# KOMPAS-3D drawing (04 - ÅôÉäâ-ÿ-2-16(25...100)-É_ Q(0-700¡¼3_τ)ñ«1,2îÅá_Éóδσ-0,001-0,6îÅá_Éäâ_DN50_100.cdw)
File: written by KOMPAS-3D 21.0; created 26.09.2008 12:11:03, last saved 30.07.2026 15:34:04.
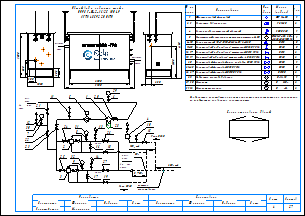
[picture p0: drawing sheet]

Sheets 1-2: A3, landscape

Document properties: Наименование: Макро:21; Автор: RaskoAdmin; Форматы листов документа: 2xA3; Полное имя файла: \\ur38nt01\Departments\КТО\КБ ПУРДГ\Заявки\Прайс-лист на типовые шкафы ГРПШ\ПУРДГ_стандарт_30_04_2026\ПУРДГ с РДГ(Н, В)\ПУРДГ-Ш-2-16(25...100)-Р_ Q(0-700нм3_ч)до1,2МПа_Рвых-0,001-0,6МПа_РДГ_DN50_100.cdw

Title block, sheet 1: Наименование: Пункт учета газа / ПУГ-Ш-400-Р / ЛГТИ.485922.001ТУ; designation: ЛГТИ.03.4411141; sheet number: 1; Количество листов документа: 2; organisation: ООО "ЭЛЬСТЕР Газэлектроника"; Форматы листов документа: A3; stored path: C:\Рабочие документы\Компас\ПУГ\Схема.cdw; Разработал: Устинов; Проверил: Кошкин; Утвердил: Кошкин
Title block, sheet 2: sheet number: 2; stored path: D:\Рабочие документы\Заявки\ПУРДГ\ПУРДГ-ШУЭО-2-100-Р 4411220.cdw; designation, second copy: ЛГТИ.03.4411141-

Views: Вид 1, Вид 2
Referenced files: wcvoit.frw
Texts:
  Normal
  № на
  схеме
  Усл.
  обозн.
  Марка
  (модель)
  Кол.
  Фильтр газовый фланцевый
  ФГ 16-50
  Регулятор давления газа
  РДГ-50
  Клапан предохранительный сбросной
  КПС DN20
  Измерительный комплекс с ротационным счетчиком Ду50
  СГ-ЭК-Р-(0,2...2,0)-
  Кран кнопочный VE-РАСКО-НЗ-1,6-G1/2-М20
  DN15
  Кран шаровой "под приварку" штуцерный DN20 PN16
  DN20
  Кран шаровой "под приварку" штуцерный DN15 PN16
  Кран шаровой "под приварку" штуцерный п/п DN20 PN16
  Кран шаровой фланцевый с мех. приводом DN50 PN16
  Кран шаровой фланцевый DN50 PN16
  Кран шаровой фланцевый DN100 PN16
  DN50
  DN100
  Индикатор перепада давления
  Манометр
  Манометр-напоромер
  Delta 15
  0...     МПа
  0...     кПа
  Общий вид и габариты шкафа
  ПУРДГ-Ш-2-16(25...100)-Р
  Выход газа
  Вход газа
  logo-rasko-ge.png
  DN 1
  местное
  сопротивление
  Римп DN20
  Выход
  газа
  Р=     кПа
  Вход
  Р=       МПа
  PDI
  Схема открывания дверей
  Предприятие изготовитель может заменять комплектующие на аналогичные,
  не ухудшающие заявленных характеристик.
  Должность
  Конструктор
  Фамилия
  Подпись
  Дата
  Согласовано
  Максимкин
  Лист
  Листов
  POLYLINE_STYLE_0.18_RGB_0_0_0
  POLYLINE_STYLE_0.50_RGB_0_0_0
  POLYLINE_STYLE_0.34_RGB_0_0_0
  PHANTOM_RGB_0_0_0_SC_1_THICK_0.18
  K5LT_THIN_RGB_0_0_0_THICK_0.18
  K5LT32769_RGB_0_0_0_THICK_0.18
  K5LT12_RGB_0_0_0_SC_1_THICK_0.18
  K5LT_DASHED_RGB_0_0_0_SC_1_THICK_0.18
  ACISOTGL_RGB_0_0_0_SC_0.8_THICK_0.25
  CONTINUOUS_RGB_0_127_31_THICK_0.3
  CONTINUOUS_RGB_0_0_255_THICK_0.35
  CONTINUOUS_RGB_255_0_0_THICK_0.35
  POLYLINE_STYLE_0.25_RGB_0_0_0
  CONTINUOUS_RGB_0_0_0_THICK_0.5
  POLYLINE_STYLE_0.35_RGB_0_0_255
  CONTINUOUS_RGB_0_0_0_THICK_0.4
  CONTINUOUS_RGB_0_0_0_THICK_0.35
  НЕВИДИМАЯ_RGB_0_0_0_SC_0.3_THICK_0.25
  СONTINUOUS_RGB_0_0_0_THICK_0.25
  ОСЕВАЯ2_RGB_248_153_30_SC_0.3_THICK_0.25
  Без оформления
Dimensions and other numbers on the sheet: 1; 2, 3; 2; 4; 5; 6-10; 11-15; 16, 17; 18, 19; 20; 21-25; 26, 27; 28; 29, 30; 31, 32; 1500; 250; 300; 1050; 550; 305; 2800; 4130; 2000; 3100; 5,,,7DN 1; 7; 30; 12; 21; 22; 23; 11; 6; 29; 24; 31; 8; 13; 26; 18; 10; 15; 25; 32; 9; 3; 14; 27; 19; 16; 17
